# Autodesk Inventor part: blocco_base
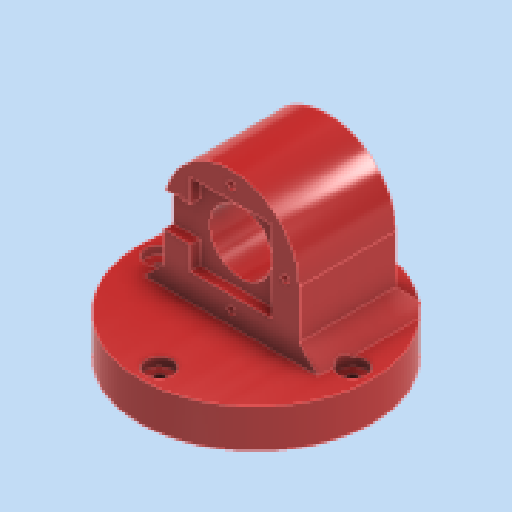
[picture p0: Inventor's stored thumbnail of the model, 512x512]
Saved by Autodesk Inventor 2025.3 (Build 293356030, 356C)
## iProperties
Created: 2026-01
Part Number: blocco_base
Material: Plastica ABS
Document SubType Name: Modeling
Designer: Ryzen5700u
Density: 1.06 g/cm^3
Appearance: Rosso
Author: Ryzen5700u
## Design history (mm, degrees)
sketch "Schizzo1"
  geometry: L1 (-35, 35)-(35, 35); L2 (35, 35)-(35, -35); L3 (35, -35)-(-35, -35); L4 (-35, -35)-(-35, 35); L5 (-35, 35)-(35, -35); L6 (35, 35)-(-35, -35); L7 (-35, 0)-(35, 0); C1 r 35 at (0, 0); 6 further points
  constraints: 14 end point, 4 midpoint, 2 parallel, 1 centre point, 1 coincident, 1 horizontal, 1 perpendicular
  dimensions: "d0" = 70 diameter of C1; "d3" = 70 distance of L2.end L3.end; "d4" = 70 distance of L1.end L2.end
extrude "Estrusione1" new body sketch "Schizzo1" distance "d1" = 50; taper "d2" = 0 deg
sketch "Schizzo2"
  geometry: 1 further point
sketch "Schizzo3"
  geometry: L1 (70, 50)-(0, 50) reference; L2 (0, 0)-(70, 0) reference; L3 (70, 0)-(70, 50) reference; L4 (0, 50)-(70, 50) reference; L5 (0, 0)-(0, 50) reference; L6 (35, 50)-(35, 0); L7 (35, 50)-(35, -34.653); C1 r 60 at (35, 37.207); 5 further points
  constraints: 4 end point, 2 midpoint, 2 point on line, 1 centre point
  dimensions: "d28" = 10 distance from line of L1 point (35, 40); "d35" = 120 diameter of C1
extrude "Estrusione2" join sketch "Schizzo3" distance "d6" = 20; taper "d7" = 0 deg
sketch "Schizzo4" dims "d9" = 100
  geometry: L1 (35, -37.207)-(35, -97.207); 3 further points
  constraints: 2 end point, 2 vertical alignment, 1 coincident, 1 point on line, 1 vertical, 3 other
hole "Foro1" sketch "Schizzo4" at (35, -87.207) diameter "d10" = 5.3; stored, may be unused: countersink angle "d14" = 90 deg, drill point angle "d16" = 118 deg; dims "d11" = 6, "d12" = 14, "d13" = 4.5, "d15" = 8
pattern_circular "Serie circolare1" dims angle "d18" = 360 deg
sketch "Schizzo5"
  geometry: C1 r 2 at (0, 28) reference; C2 r 1.571 at (0, -28) reference; C3 r 1.571 at (26.833, 8); C4 r 1.571 at (-28, 0) reference; C5 r 1.571 at (26.833, 8) reference; 1 further point
  constraints: 1 centre point, 1 coincident
hole "Foro2" sketch "Schizzo5" at (0, 28), (-28, 0), (26.833, 8), (0, -28) diameter "d20" = 4.3; stored, may be unused: countersink angle "d24" = 90 deg, drill point angle "d26" = 118 deg; dims "d21" = 6, "d22" = 12, "d23" = 30, "d25" = 8
chamfer "Smusso1" distance "d29" = 10; stored, may be unused: second distance "d30" = 2, angle "d31" = 45 deg
sketch "Schizzo6"
  geometry: C1 r 16 at (0, 0); 1 further point
  constraints: 1 centre point, 1 coincident
  dimensions: "d32" = 32 diameter of C1
extrude "Estrusione3" cut sketch "Schizzo6" extent not by distance; stored distance "d33" = 0; taper "d34" = 0 deg
sketch "Schizzo7"
  geometry: L1 (-21.1, 21.1)-(21.1, 21.1); L2 (21.1, 21.1)-(21.1, -21.1); L3 (21.1, -21.1)-(-21.1, -21.1); L4 (-21.1, -21.1)-(-21.1, 21.1); L5 (-21.1, 21.1)-(21.1, -21.1); L6 (21.1, 21.1)-(-21.1, -21.1); 1 further point
  constraints: 12 end point, 2 midpoint, 2 parallel, 1 horizontal, 1 perpendicular
  dimensions: "d42" = 42.2 distance of L2.end L3.end; "d43" = 42.2 distance of L1.end L2.end
extrude "Estrusione4" cut sketch "Schizzo7" distance "d44" = 5; taper "d45" = 0 deg
sketch "Schizzo8"
  geometry: L1 (-33.823, -9)-(-21.1, -9) reference; L2 (-28.736, 9)-(-33.823, 9) reference; L3 (21.1, 21.1)-(21.1, -21.1) reference; L4 (21.1, -21.1)-(-21.1, -21.1) reference; L5 (-21.1, -21.1)-(-21.1, 21.1) reference; L6 (-21.1, 21.1)-(21.1, 21.1) reference; L7 (-35, 0)-(-35, -25) reference; L8 (-45, -35)-(-35, -25) reference; L9 (-45, -35)-(45, -35) reference; L10 (35, -25)-(45, -35) reference; L11 (35, -25)-(35, 0) reference; L12 (-33.823, 9)-(-21.1, 9); L13 (-21.1, -21.1)-(-21.1, 21.1) reference; L14 (-21.1, -9)-(-35, -9); C1 r 2.15 at (0, -28) reference; C2 r 2.15 at (-26.833, 8) reference; C3 r 2.15 at (28, 0) reference; C4 r 2.15 at (0, 28) reference; A1 r 35 centre (0, 0) between (35, 0) and (-35, 0) reference; 7 further points
  constraints: 4 end point, 2 perpendicular, 2 point on line
  node "Riferimento6"
  node "Riferimento7"
  node "Linea chiusa proiettata3"
sketch "Schizzo9"
  geometry: L1 (21.1, 21.1)-(21.1, -21.1) reference; L2 (21.1, -21.1)-(-21.1, -21.1) reference; L3 (-21.1, -21.1)-(-21.1, 21.1) reference; L4 (-21.1, 21.1)-(21.1, 21.1) reference; L5 (-35, 0)-(-35, -25) reference; L6 (-45, -35)-(-35, -25) reference; L7 (-45, -35)-(45, -35) reference; L8 (35, -25)-(45, -35) reference; L9 (35, -25)-(35, 0) reference; C1 r 2.15 at (0, -28) reference; C2 r 2.15 at (-26.833, 8) reference; C3 r 2.15 at (28, 0) reference; C4 r 2.15 at (0, 28) reference; A1 r 35 centre (0, 0) between (35, 0) and (-35, 0) reference; 1 further point
  node "Linea chiusa proiettata2"
extrude "Estrusione5" cut sketch "Schizzo8" distance "d46" = 5; taper "d47" = 0 deg
node "Solido1"
node "Linea chiusa proiettata1"
node "Riferimento1"
node "Riferimento2"
node "Riferimento4"
node "Riferimento5"
